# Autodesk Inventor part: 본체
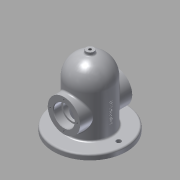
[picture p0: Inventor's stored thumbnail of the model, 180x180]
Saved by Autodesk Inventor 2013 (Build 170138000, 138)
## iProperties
Created: 2019-11
Part Number: 본체
Material: 알루미늄 6061
Document SubType Name: Modeling
Designer: Administrator
Density: 2.71 g/cm^3
Mass: 1110.24 g
Surface Area: 883.324 cm^2
Volume: 409.682 cm^3
Author: Administrator
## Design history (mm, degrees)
sketch "스케치1"
  geometry: C1 r 70 at (0, 0); 1 further point
  constraints: 1 centre point, 1 coincident
  dimensions: "d0" = 140 diameter of C1
extrude "돌출1" new body sketch "스케치1" distance "d2" = 10; taper "d3" = 0 deg
sketch "스케치3"
  geometry: C1 r 70 at (0, 0) reference; C2 r 40 at (0, 0)
  constraints: 1 centre point, 1 coincident
  dimensions: "d12" = 80 diameter of C2
extrude "돌출2" join sketch "스케치3" distance "d14" = 120; taper "d15" = 0 deg
sketch "스케치4"
  geometry: L1 (0, 0)-(-55, 0); L2 (0, 0)-(55, 0); C1 r 70 at (0, 0) reference; C2 r 4.5 at (-55, 0); C3 r 4.5 at (55, 0); A1 r 55 centre (0, 0) between (-55, 0) and (55, 0)
  constraints: 4 end point, 3 centre point, 3 coincident, 2 point on circle, 1 collinear, 1 equal radius, 1 horizontal
  dimensions: "d17" = 110 diameter of A1; "d20" = 9 diameter of C2
extrude "돌출3" cut sketch "스케치4" distance "d21" = 10; taper "d22" = 0 deg
sketch "스케치5"
  geometry: C1 r 70 at (0, 0) reference; C2 r 30 at (0, 0)
  constraints: 1 centre point, 1 coincident
  dimensions: "d23" = 60 diameter of C2
extrude "돌출4" cut sketch "스케치5" distance "d25" = 120; taper "d26" = 0 deg
node "작업 평면1"
sketch "스케치6"
  geometry: L1 (0, 0)-(0, 50); L2 (-70, 0)-(70, 0) reference; C1 r 31 at (0, 50)
  constraints: 2 end point, 1 centre point, 1 coincident, 1 perpendicular
  dimensions: "d29" = 50 distance of L1.start L1.end; "d30" = 62 diameter of C1
extrude "돌출5" join sketch "스케치6" stored distance "d31" = 120; taper "d32" = 0 deg
node "작업 평면2"
sketch "스케치7"
  geometry: L1 (0, 0)-(0, 50); C1 r 31 at (0, 50)
  constraints: 2 end point, 1 centre point, 1 coincident, 1 vertical
  dimensions: "d34" = 50 distance of L1.start L1.end; "d35" = 62 diameter of C1
extrude "돌출6" join sketch "스케치7" stored distance "d36" = 120; taper "d37" = 0 deg
sketch "스케치8"
  geometry: C1 r 31 at (0, 0) reference; C2 r 20 at (0, 0); 1 further point
  constraints: 1 centre point, 1 coincident
  dimensions: "d38" = 40 diameter of C2
extrude "돌출7" cut sketch "스케치8" distance "d40" = 15; taper "d41" = 0 deg
sketch "스케치9"
  geometry: C1 r 31 at (0, 0) reference; C2 r 20 at (0, 0); 1 further point
  constraints: 1 centre point, 1 coincident
  dimensions: "d42" = 40 diameter of C2
extrude "돌출8" cut sketch "스케치9" distance "d44" = 15; taper "d45" = 0 deg
sketch "스케치10"
  geometry: C1 r 20 at (0, 0) reference; C2 r 16.5 at (0, 0); 1 further point
  constraints: 1 centre point, 1 coincident
  dimensions: "d46" = 33 diameter of C2
extrude "돌출9" cut sketch "스케치10" stored distance "d48" = 15; taper "d49" = 0 deg
sketch "스케치11"
  geometry: C1 r 20 at (0, 0) reference; C2 r 16.5 at (0, 0); 1 further point
  constraints: 1 centre point, 1 coincident
  dimensions: "d50" = 33 diameter of C2
extrude "돌출10" cut sketch "스케치11" stored distance "d52" = 15; taper "d53" = 0 deg
fillet "모깎기3" dims "d55" = 40
fillet "모깎기4" dims "d56" = 30
node "작업 평면4"
sketch "스케치12"
  geometry: C1 r 7.5 at (0, 0); 1 further point
  constraints: 1 centre point, 1 coincident
  dimensions: "d58" = 15 diameter of C1
extrude "돌출11" join sketch "스케치12" stored distance "d60" = 15; taper "d61" = 0 deg
sketch "스케치13"
  geometry: C1 r 7.5 at (0, 0) reference
hole "구멍1" sketch "스케치13" at (0, 0) diameter "d62" = 5.188; stored, may be unused: countersink angle "d66" = 90 deg, drill point angle "d68" = 0 deg; dims "d63" = 6, "d64" = 4, "d65" = 2, "d67" = 8
sketch "스케치14" dims "d44" = 15, "d45" = 0
  geometry: L1 (0, 0)-(0, 26); L2 (0, 0)-(0, -26); L3 (0, 0)-(-26, 0); L4 (0, 0)-(26, 0); C1 r 31 at (0, 0) reference; A1 r 26 centre (0, 0) between (0, 26) and (0, -26); 1 further point
  constraints: 8 end point, 4 point on circle, 2 collinear, 1 centre point, 1 coincident, 1 perpendicular, 1 vertical
  dimensions: "d69" = 52 diameter of A1
hole "구멍2" sketch "스케치14" at (0, 26), (-26, 0), (0, -26), (26, 0) diameter "d71" = 3.242; stored, may be unused: countersink angle "d75" = 90 deg, drill point angle "d77" = 118 deg; dims "d72" = 8, "d73" = 4, "d74" = 2, "d76" = 10
sketch "스케치15" dims "d78" = 52
  geometry: L1 (0, 0)-(0, 26); L2 (0, 0)-(-26, 0); L3 (0, 0)-(26, 0); L4 (0, 0)-(0, -26); C1 r 31 at (0, 0) reference
  constraints: 8 end point, 2 perpendicular, 1 coincident, 1 collinear, 1 horizontal alignment, 1 vertical, 2 other
hole "구멍3" sketch "스케치15" at (0, -26), (26, 0), (0, 26), (-26, 0) diameter "d80" = 3.242; stored, may be unused: countersink angle "d84" = 90 deg, drill point angle "d86" = 118 deg; dims "d81" = 8, "d82" = 4, "d83" = 2, "d85" = 10
chamfer "모따기1" distance "d87" = 1; stored, may be unused: second distance "d88" = 2, angle "d89" = 45 deg
chamfer "모따기2" distance "d90" = 1; stored, may be unused: second distance "d91" = 2, angle "d92" = 45 deg
fillet "모깎기5" dims "d93" = 0.3, "d94" = 3
node "작업 평면5"
sketch "스케치17"
  geometry: L1 (0, -10)-(0, 40); L2 (30, -10)-(-30, -10) reference; 2 further points
  constraints: 2 end point, 1 perpendicular, 1 other
  dimensions: "d96" = 50 distance of L1.start L1.end
feature "엠보싱1" sketch "스케치17" dims "d97" = 0.5, "d98" = 0
node "솔리드1"
other parameters: "d57" = 135
